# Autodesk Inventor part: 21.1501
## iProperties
Created: 2006-12
Part Number: 21.1501
Material: Steel, Mild
Description: M4x16 C'SUNK
Document SubType Name: Modeling
Standard: DIN 7991
Designer: Andy Moles
Standards Organization: DIN
Language: en-US
Size Designation: M4x16
Categories: <MemberInstance Version="R10.0.0"><Categories><Category DisplayName="Fasteners" InternalName="e4da775c-781d-43d5-af7c-5136215cf5a6" Mnemonic="FSTN"><Category Di
Density: 7.86 g/cm^3
Vendor: S
Mass: 1.85044 g
Surface Area: 3.08594 cm^2
Volume: 0.235425 cm^3
Author: Andy Moles
Revision Number: 1
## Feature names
1. Revolution1
2. Extrusion1
3. Fillet1
4. Chamfer1
